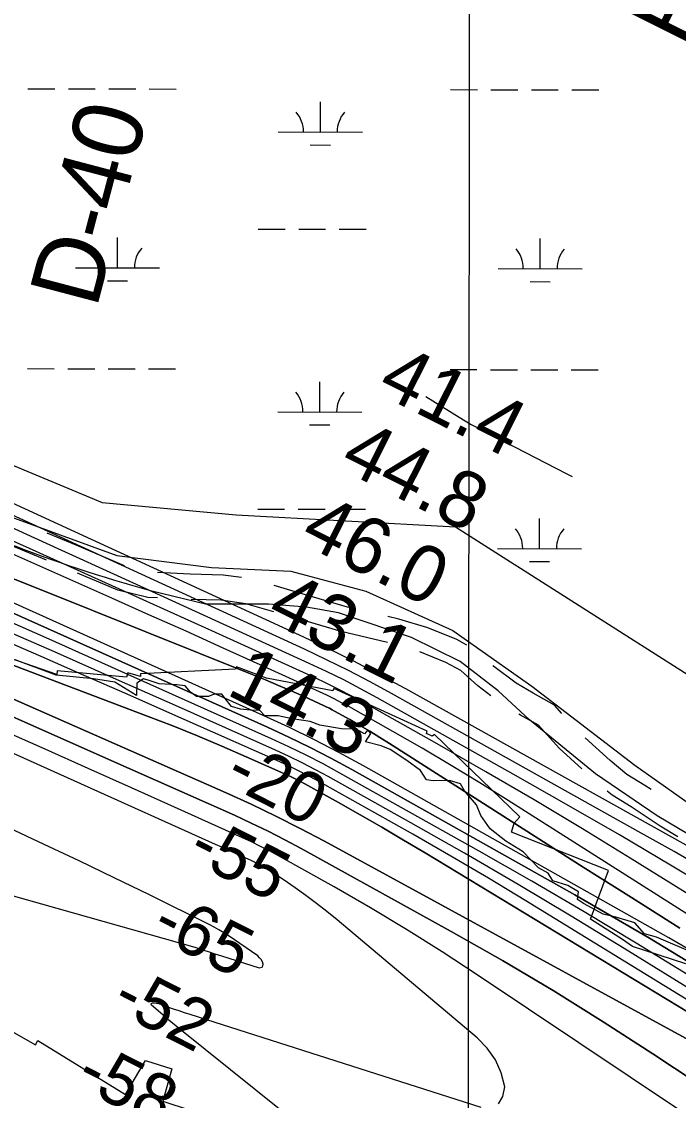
# Model space of a CAD drawing. Extents: x 3219052 to 3256913, y 800770 to 826146.
# Drawn here: x 3238412 to 3239192, y 815198 to 816480 of the extents above; entities that cross this region are included whole.
import ezdxf

# ---------------------------------------------------------------- set-up
doc = ezdxf.new("R2010")
doc.units = 0
for name, color, linetype in [('V-GRID-MAJR', 7, 'Continuous'), ('V-RIVR-EDGE', 7, 'Continuous'), ('V-RIVR-RANG', 7, 'Continuous'), ('V-RIVR-RANG-IDEN', 7, 'Continuous'), ('V-ROAD-CNTR', 7, 'Continuous'), ('V-RRAP-RVMT', 7, 'Continuous'), ('V-SITE-VEGE', 7, 'Continuous'), ('V-TOPO-DPTH', 7, 'Continuous'), ('V-TOPO-MAJR', 7, 'Continuous'), ('V-TOPO-MINR', 7, 'Continuous'), ('V-TOPO-WATR', 7, 'Continuous'), ('V-WETL-SWMP', 7, 'Continuous')]:
    doc.layers.add(name, color=color, linetype=linetype)

msp = doc.modelspace()

# ---------------------------------------------------------------- linework, layer by layer
at = {"layer": 'V-GRID-MAJR'}
msp.add_spline([(3238932.4, 806165.2), (3238939.4, 812224), (3238946.5, 818286.2), (3238953.5, 824348.4), (3238953.5, 824351.8)], degree=3, dxfattribs=at)
at = {"layer": 'V-RIVR-EDGE'}
for points in [[(3239117.7, 815415.8), (3239102.5, 815419.3), (3239079.5, 815432), (3239072.1, 815436.8), (3239073.5, 815445.9), (3239060.9, 815453.3), (3239043.1, 815459), (3239037.4, 815468.1), (3239025.7, 815474.3), (3239007.5, 815493.4), (3238987.1, 815506.1), (3238968.5, 815520.9), (3238957.2, 815536.6), (3238952.4, 815549.2), (3238938.1, 815565.8), (3238933.4, 815574), (3238920.3, 815578), (3238900.8, 815577.6), (3238893, 815578.9), (3238885.6, 815590.2), (3238869.5, 815602), (3238849.6, 815615.1), (3238839.2, 815619.5), (3238820.5, 815623.9), (3238826.6, 815633.8), (3238823.1, 815638.2), (3238819.2, 815633.4), (3238812.7, 815637.3), (3238807.9, 815639.1), (3238791.8, 815639.6), (3238766.2, 815644), (3238754.5, 815648.4), (3238733.2, 815651.5), (3238716.7, 815655), (3238701, 815655), (3238695, 815661.5), (3238683.7, 815661.6), (3238671.9, 815662.9), (3238661.1, 815666), (3238653.7, 815675.6), (3238649.8, 815680.8), (3238640.7, 815680.8), (3238634.1, 815677.8), (3238619.8, 815677.8), (3238612.4, 815683.1), (3238606.4, 815690.5), (3238596.4, 815691.8), (3238575.5, 815693.1), (3238563.3, 815697.1), (3238556.8, 815698.8), (3238549, 815693.6), (3238548.5, 815679.3), (3238522.9, 815695), (3238497.3, 815699), (3238452.9, 815703.4), (3238404.3, 815721.4)], [(3239204.1, 815375.6), (3239165.9, 815391.8), (3239151.6, 815396.1), (3239140.3, 815409.2), (3239117.7, 815415.8)]]:
    msp.add_lwpolyline(points, dxfattribs=at)
at = {"layer": 'V-ROAD-CNTR'}
for points in [[(3238441.5, 815839.9), (3238399.5, 815857.4), (3238347.3, 815872.9)], [(3238534.3, 815833.2), (3238476.8, 815857.7), (3238442.2, 815872.1)], [(3238566.7, 815803.2), (3238555.6, 815806.2), (3238544.6, 815809.4), (3238533.6, 815812.5), (3238522.7, 815815.8), (3238511.7, 815819.2), (3238500.8, 815822.6), (3238489.9, 815826.1), (3238479, 815829.6), (3238468.2, 815833.3), (3238457.4, 815837), (3238446.6, 815840.8), (3238435.8, 815844.7), (3238425.1, 815848.6), (3238414.4, 815852.7), (3238403.7, 815856.8)], [(3238573.3, 815795.2), (3238561.9, 815795.7), (3238526.1, 815804.1), (3238478.4, 815824.4)], [(3238673.1, 815819.2), (3238651.5, 815822.3), (3238612.1, 815823.4), (3238573.4, 815825.2)], [(3239794.4, 815150.8), (3239388.8, 815404.4), (3239166.9, 815536), (3239093.4, 815585.9), (3239015.1, 815650.4), (3238978, 815684.8), (3238932.9, 815719.4), (3238874.9, 815748), (3238822.4, 815765.9), (3238788.2, 815777.5), (3238750.3, 815784), (3238705.1, 815787.6), (3238630.2, 815787.6), (3238566.7, 815803.2)], [(3238808, 815782.1), (3238799.1, 815784.2), (3238731.9, 815804), (3238711.9, 815809.7)], [(3238711.6, 815778.6), (3238678.1, 815788.2), (3238649, 815792.3), (3238613.2, 815793.4)], [(3238940.6, 815739.1), (3238929, 815745.6), (3238894.3, 815759.5), (3238860, 815769.8), (3238846.9, 815772.9)], [(3238846.7, 815742.1), (3238791.4, 815755.2), (3238750, 815767.4)], [(3238969.3, 815678.9), (3238953.9, 815690.6), (3238933.7, 815708.7), (3238916, 815718.5), (3238885, 815730.9)], [(3239053.6, 815657.8), (3239044.9, 815667.5), (3239019.6, 815681.9), (3238999.4, 815693.6), (3238973, 815713.7), (3238972, 815714.6)], [(3239077.5, 815591.9), (3239050.5, 815616.6), (3239025.9, 815643.8), (3239004.7, 815655.9), (3239002.7, 815657.1)], [(3239159.6, 815567.3), (3239152.3, 815572.3), (3239130.8, 815585.2), (3239110.9, 815601.9), (3239081.3, 815629)], [(3239191.5, 815511.3), (3239170.5, 815523.7), (3239136.1, 815547), (3239113.3, 815560.7), (3239107.6, 815565.5)]]:
    msp.add_lwpolyline(points, dxfattribs=at)
at = {"layer": 'V-RRAP-RVMT'}
for points in [[(3237377.9, 815921.9), (3237418.6, 815904.3), (3237423.2, 815901.5), (3237419.2, 815888.9), (3237430.6, 815884.4), (3237430.1, 815883.5), (3237533.8, 815818), (3237531.6, 815812.2), (3237547.5, 815806.1), (3237544, 815796.2), (3237571.4, 815784.5), (3237560.1, 815763.9), (3237653, 815706.7), (3237656, 815712.1), (3237928.6, 815546.1), (3237929.8, 815548), (3237935.3, 815544.9), (3237933.7, 815539.8), (3237961.3, 815530.1), (3238428.6, 815264.2), (3238431.4, 815269.1)], [(3239087.5, 815413.2), (3239109.2, 815471.1), (3238993.9, 815516.6), (3238996.8, 815527.3), (3239003.7, 815534.8), (3238902.4, 815632.6), (3238899.4, 815630.8), (3238892.9, 815634.1), (3238893.8, 815636.6), (3238782.9, 815687.6), (3238781.5, 815684.6), (3238703, 815699.6), (3238667.1, 815713.1), (3238666, 815710.3), (3238553.2, 815704.7), (3238553.2, 815701.7), (3238538, 815706.1), (3238536.6, 815700.9), (3238454.2, 815708.5), (3238453.8, 815704.1), (3238294, 815759.4)], [(3239201, 815360.4), (3239137.5, 815380.7), (3239125.5, 815389.2), (3239087.5, 815413.2)], [(3238431.4, 815269.1), (3238535.4, 815204.9), (3238559.2, 815245.3), (3238590.6, 815235.4), (3238579.8, 815197), (3238707, 815155.3), (3238697.4, 815118.5), (3238826.8, 815078.9), (3238818.9, 815052.1), (3238942.7, 815013.5)]]:
    msp.add_lwpolyline(points, dxfattribs=at)
at = {"layer": 'V-SITE-VEGE'}
msp.add_lwpolyline([(3237307.9, 816549.6), (3237406.5, 816486.8), (3237522.9, 816415.1), (3237630.5, 816370.2), (3237738, 816343.3), (3237791.8, 816316.4), (3237827.6, 816244.7), (3237917.2, 816190.9), (3238006.8, 816119.1), (3238078.5, 816056.4), (3238114.3, 816032.5), (3238318.4, 815920.7), (3238525, 815845.5), (3238637.7, 815831.4), (3238731.6, 815826.7), (3238820.9, 815803.2), (3238924.2, 815756.2), (3239018.1, 815690.4), (3239140.2, 815596.4), (3239220, 815540)], dxfattribs=at)
at = {"layer": 'V-TOPO-DPTH'}
for points in [[(3238375.2, 815828.5), (3238433.1, 815805.3), (3238686, 815704), (3238701.5, 815697.7), (3238716.9, 815691.2), (3238732.1, 815684.6), (3238747.4, 815677.8), (3238771.5, 815666.9), (3238774.6, 815665.4), (3238777.7, 815663.9), (3238780.7, 815662.3), (3238783.7, 815660.7), (3238801.8, 815650.5), (3238813.7, 815643.6), (3238825.6, 815636.6), (3238837.4, 815629.4), (3238849, 815622), (3238964.8, 815548.2), (3239021.9, 815511.7), (3239079.1, 815475.3), (3239136.3, 815439), (3239193.6, 815402.7)], [(3238388.9, 815783.1), (3238703.9, 815641.6), (3238729.4, 815629.8), (3238754.6, 815617.5), (3238779.4, 815604.6), (3238804, 815591.2), (3239069, 815442.2), (3239113.5, 815416.7), (3239157.6, 815390.8), (3239201.4, 815364.2)], [(3239201.4, 815364.2), (3239157.6, 815390.8), (3239113.5, 815416.7), (3239069, 815442.2), (3238804, 815591.2), (3238779.4, 815604.6), (3238754.6, 815617.5), (3238729.4, 815629.8), (3238703.9, 815641.6), (3238388.9, 815783.1)], [(3239287, 815279.9), (3239127.6, 815378.7), (3239064.8, 815417), (3239001.7, 815454.7), (3238938.1, 815491.6), (3238874.1, 815528), (3238776.2, 815582.7), (3238760.9, 815591), (3238745.3, 815599), (3238729.6, 815606.7), (3238713.7, 815614), (3238598.4, 815665.5), (3238524.7, 815698.3), (3238450.9, 815730.9), (3238377.1, 815763.3)], [(3239287, 815279.9), (3239127.6, 815378.7), (3239064.8, 815417), (3239001.7, 815454.7), (3238938.1, 815491.6), (3238874.1, 815528), (3238776.2, 815582.7), (3238760.9, 815591), (3238745.3, 815599), (3238729.6, 815606.7), (3238713.7, 815614), (3238598.4, 815665.5), (3238524.7, 815698.3), (3238450.9, 815730.9), (3238377.1, 815763.3)], [(3238317, 815747.3), (3238562.3, 815654.3), (3238591.6, 815642.9), (3238620.8, 815631.2), (3238649.9, 815618.9), (3238678.7, 815606.4), (3238723.6, 815586.5), (3238729.9, 815583.6), (3238736.1, 815580.6), (3238742.3, 815577.4), (3238748.4, 815574.1), (3238788.3, 815551.9), (3238814.2, 815537.3), (3238840, 815522.5), (3238865.7, 815507.4), (3238891.2, 815492.2), (3239296.3, 815246.6)], [(3238317, 815747.3), (3238562.3, 815654.3), (3238591.6, 815642.9), (3238620.8, 815631.2), (3238649.9, 815618.9), (3238678.7, 815606.4), (3238723.6, 815586.5), (3238729.9, 815583.6), (3238736.1, 815580.6), (3238742.3, 815577.4), (3238748.4, 815574.1), (3238788.3, 815551.9), (3238814.2, 815537.3), (3238840, 815522.5), (3238865.7, 815507.4), (3238891.2, 815492.2), (3239296.3, 815246.6)], [(3239209.1, 815267.2), (3238771.6, 815506), (3238742.8, 815521.2), (3238713.9, 815535.9), (3238684.5, 815549.9), (3238655, 815563.4), (3238285.1, 815726.3)], [(3238285.1, 815726.3), (3238655, 815563.4), (3238684.5, 815549.9), (3238713.9, 815535.9), (3238742.8, 815521.2), (3238771.6, 815506), (3239209.1, 815267.2)], [(3239240.2, 815201.5), (3239161.6, 815253.5), (3239102.8, 815291.5), (3239043.4, 815328.5), (3238983.1, 815364.1), (3238922.3, 815398.7), (3238744.2, 815497.2), (3238724.6, 815507.7), (3238704.9, 815517.9), (3238684.8, 815527.5), (3238664.7, 815536.8), (3238508.4, 815606.3), (3238422.2, 815644.6), (3238336, 815682.8)], [(3238336, 815682.8), (3238422.2, 815644.6), (3238508.4, 815606.3), (3238664.7, 815536.8), (3238684.8, 815527.5), (3238704.9, 815517.9), (3238724.6, 815507.7), (3238744.2, 815497.2), (3238922.3, 815398.7), (3238983.1, 815364.1), (3239043.4, 815328.5), (3239102.8, 815291.5), (3239161.6, 815253.5), (3239240.2, 815201.5)]]:
    msp.add_lwpolyline(points, dxfattribs=at)
at = {"layer": 'V-TOPO-MAJR'}
for points in [[(3239247.2, 815438.6), (3239184.8, 815476.2), (3239122.1, 815513.4), (3239059, 815549.8), (3238995.6, 815585.8), (3238834.4, 815676.3), (3238814.5, 815687.1), (3238794.5, 815697.6), (3238774.2, 815707.6), (3238753.7, 815717.3), (3238530.3, 815819.4), (3238455.5, 815853.5), (3238380.5, 815887.5)], [(3239255.4, 815144.8), (3238953.2, 815347.2), (3238911.4, 815374.5), (3238869.2, 815401.1), (3238826.4, 815426.7), (3238783.2, 815451.6), (3238717, 815488.7), (3238706.5, 815494.4), (3238695.9, 815499.9), (3238685.1, 815505.1), (3238674.3, 815510.2), (3238593.7, 815546.3), (3238542.5, 815569.3), (3238491.2, 815592.3), (3238440, 815615.2), (3238388.7, 815638.1)]]:
    msp.add_lwpolyline(points, dxfattribs=at)
at = {"layer": 'V-TOPO-MINR'}
for points in [[(3238892, 816034.3), (3238931.8, 816009.8), (3238938.9, 816005.5), (3238946, 816001.3), (3238953.2, 815997.4), (3238960.6, 815993.5), (3239059.4, 815942.5), (3239065.9, 815939.4)], [(3239304, 815444), (3238868.3, 815686.9), (3238837.1, 815703.8), (3238805.7, 815720.2), (3238774, 815735.8), (3238741.9, 815751), (3238168.5, 816014.6)], [(3239342.9, 815330.3), (3238990, 815554.2), (3238956.1, 815575.4), (3238922, 815596.1), (3238887.6, 815616.4), (3238853, 815636.3), (3238800.6, 815665.9), (3238792, 815670.6), (3238783.3, 815675.1), (3238774.5, 815679.5), (3238765.6, 815683.6), (3238695.4, 815715.5), (3238651.4, 815735.5), (3238607.3, 815755.4), (3238563.2, 815775.1), (3238519, 815794.8), (3238126.8, 815969.2)], [(3237309.9, 815963.6), (3237398.2, 815910.1), (3237485.9, 815855.7), (3237572.6, 815799.8), (3237658.8, 815743.1), (3237881.1, 815585.8), (3237889.5, 815583.3), (3237918.4, 815577.3), (3237922.5, 815576.6), (3238617.8, 815380.1), (3238625.7, 815377.4), (3238633.5, 815374.8), (3238641.3, 815372.2), (3238649.2, 815369.7), (3238694.2, 815355.7), (3238697.8, 815356.4)], [(3239225.9, 815471.3), (3239187, 815493.6), (3239148, 815515.7), (3238851.3, 815681.6), (3238825.8, 815695.4), (3238800.1, 815708.9), (3238774.1, 815721.7), (3238747.8, 815734.1), (3238351.5, 815915.8)], [(3239291.7, 815262.9), (3239010.8, 815435), (3238966.4, 815461.9), (3238921.8, 815488.3), (3238876.8, 815514.2), (3238831.6, 815539.8), (3238762.3, 815578.4), (3238751.6, 815584.2), (3238740.7, 815589.8), (3238729.7, 815595.1), (3238718.7, 815600.2), (3238639.2, 815635.6), (3238588.2, 815658.2), (3238537.2, 815680.7), (3238486.2, 815703), (3238435.1, 815725.3), (3238084.7, 815877.4)], [(3239333.8, 815362.1), (3239134.8, 815485.8), (3239078, 815520.6), (3239020.8, 815555), (3238963.3, 815588.5), (3238905.4, 815621.6), (3238817.5, 815671.1), (3238803.2, 815678.8), (3238788.9, 815686.4), (3238774.3, 815693.5), (3238759.7, 815700.4), (3238642.2, 815754), (3238568.7, 815787.4), (3238495.1, 815820.6), (3238421.5, 815853.8), (3238347.8, 815886.7)], [(3239207.1, 815375.7), (3239180.5, 815391), (3238817.9, 815595.4), (3238788.7, 815611.3), (3238759.2, 815626.8), (3238729.2, 815641.4), (3238699, 815655.5), (3238248, 815858.7)], [(3239193.6, 815402.7), (3239136.3, 815439), (3239079.1, 815475.3), (3239021.9, 815511.7), (3238964.8, 815548.2), (3238849, 815622), (3238837.4, 815629.4), (3238825.6, 815636.6), (3238813.7, 815643.6), (3238801.8, 815650.5), (3238783.7, 815660.7), (3238780.7, 815662.3), (3238777.7, 815663.9), (3238774.6, 815665.4), (3238771.5, 815666.9), (3238747.4, 815677.8), (3238732.1, 815684.6), (3238716.9, 815691.2), (3238701.5, 815697.7), (3238686, 815704), (3238433.1, 815805.3), (3238375.2, 815828.5)], [(3239203.4, 815347.1), (3239142, 815385), (3239080.3, 815422.2), (3239018, 815458.6), (3238955.4, 815494.3), (3238790.1, 815586.9), (3238770.1, 815597.8), (3238749.9, 815608.3), (3238729.5, 815618.2), (3238708.8, 815627.8), (3238526.6, 815709.4), (3238444.7, 815745.9), (3238362.8, 815782.3)], [(3238978.5, 815194.1), (3238983.6, 815202.6), (3238986, 815214.2), (3238981.4, 815230.9), (3238974.8, 815246.3), (3238965, 815260), (3238953.1, 815272.5), (3238786.7, 815412.4), (3238774.5, 815422.3), (3238762.3, 815432), (3238749.7, 815441.3), (3238737, 815450.4), (3238722.8, 815460.3), (3238717, 815464.2), (3238711.1, 815468), (3238705.2, 815471.6), (3238699.1, 815475.1), (3238689.9, 815480.3), (3238688.4, 815481.1), (3238685.4, 815482.6), (3238683.9, 815483.4), (3238672, 815488.7), (3238664.6, 815492.1), (3238657.1, 815495.5), (3238649.6, 815498.9), (3238642.1, 815502.2), (3238046.9, 815770.4)], [(3239287, 815279.9), (3239127.6, 815378.7), (3239064.8, 815417), (3239001.7, 815454.7), (3238938.1, 815491.6), (3238874.1, 815528), (3238776.2, 815582.7), (3238760.9, 815591), (3238745.3, 815599), (3238729.6, 815606.7), (3238713.7, 815614), (3238598.4, 815665.5), (3238524.7, 815698.3), (3238450.9, 815730.9), (3238377.1, 815763.3)], [(3239296.3, 815246.6), (3238891.2, 815492.2), (3238865.7, 815507.4), (3238840, 815522.5), (3238814.2, 815537.3), (3238788.3, 815551.9), (3238748.4, 815574.1), (3238742.3, 815577.4), (3238736.1, 815580.6), (3238729.9, 815583.6), (3238723.6, 815586.5), (3238678.7, 815606.4), (3238649.9, 815618.9), (3238620.8, 815631.2), (3238591.6, 815642.9), (3238562.3, 815654.3), (3238317, 815747.3)], [(3239209.1, 815267.2), (3238771.6, 815506), (3238742.8, 815521.2), (3238713.9, 815535.9), (3238684.5, 815549.9), (3238655, 815563.4), (3238285.1, 815726.3)], [(3239240.2, 815201.5), (3239161.6, 815253.5), (3239102.8, 815291.5), (3239043.4, 815328.5), (3238983.1, 815364.1), (3238922.3, 815398.7), (3238744.2, 815497.2), (3238724.6, 815507.7), (3238704.9, 815517.9), (3238684.8, 815527.5), (3238664.7, 815536.8), (3238508.4, 815606.3), (3238422.2, 815644.6), (3238336, 815682.8)], [(3238697.8, 815356.4), (3238698.6, 815357.9), (3238698.9, 815359.9), (3238698, 815362.8), (3238696.6, 815365.4), (3238694.7, 815367.6), (3238692.5, 815369.6), (3238657.5, 815393.8), (3238652, 815397.3), (3238646.4, 815400.8), (3238640.7, 815404), (3238634.9, 815407), (3238563.7, 815442.1), (3238522.1, 815462.4), (3238480.4, 815482.5), (3238438.6, 815502.2), (3238396.7, 815521.8)], [(3238812.5, 815111.8), (3238600, 815282.5), (3238595.6, 815286.1), (3238591.1, 815289.8), (3238586.7, 815293.5), (3238582.4, 815297.2), (3238566.4, 815311), (3238566, 815312), (3238566, 815312.9), (3238566.6, 815313.5), (3238567.6, 815314), (3238569.9, 815313.8), (3238574.5, 815313), (3238576.8, 815312.3), (3238585.4, 815309.3), (3238592, 815307), (3238598.6, 815304.8), (3238605.2, 815302.6), (3238611.8, 815300.4), (3238957.4, 815189.8)]]:
    msp.add_lwpolyline(points, dxfattribs=at)
at = {"layer": 'V-TOPO-WATR'}
msp.add_lwpolyline([(3239201.4, 815364.2), (3239157.6, 815390.8), (3239113.5, 815416.7), (3239069, 815442.2), (3238804, 815591.2), (3238779.4, 815604.6), (3238754.6, 815617.5), (3238729.4, 815629.8), (3238703.9, 815641.6), (3238388.9, 815783.1)], dxfattribs=at)
at = {"layer": 'V-WETL-SWMP'}
for p, q in [((3238419.5, 816400.2), (3238451.5, 816400.1)), ((3238467.5, 816400.1), (3238499.5, 816400)), ((3238515.5, 816400), (3238547.5, 816399.9)), ((3238563.5, 816399.9), (3238595.5, 816399.8)), ((3238921.4, 816399.1), (3238953.4, 816399)), ((3238969.4, 816399), (3239001.4, 816398.9)), ((3239017.4, 816398.9), (3239049.4, 816398.8)), ((3239065.4, 816398.8), (3239097.4, 816398.7)), ((3238766.8, 816348.7), (3238766.8, 816384.7)), ((3238716.8, 816348.8), (3238816.8, 816348.6)), ((3238754.7, 816333.3), (3238778.7, 816333.2)), ((3238693.1, 816233.4), (3238725.1, 816233.4)), ((3238525.9, 816187.3), (3238526, 816223.3)), ((3238741.1, 816233.3), (3238773.1, 816233.3)), ((3238789.1, 816233.2), (3238821.1, 816233.2)), ((3239027.8, 816186.3), (3239027.9, 816222.3)), ((3238475.9, 816187.4), (3238575.9, 816187.2)), ((3238977.8, 816186.4), (3239077.8, 816186.2)), ((3238513.9, 816171.9), (3238537.9, 816171.9)), ((3239015.8, 816170.9), (3239039.8, 816170.8)), ((3238418.8, 816067.5), (3238450.8, 816067.4)), ((3238466.8, 816067.4), (3238498.8, 816067.3)), ((3238514.8, 816067.3), (3238546.8, 816067.2)), ((3238562.8, 816067.2), (3238594.8, 816067.1)), ((3238920.8, 816066.4), (3238952.8, 816066.4)), ((3238968.8, 816066.3), (3239000.8, 816066.3)), ((3239016.8, 816066.2), (3239048.8, 816066.2)), ((3239064.8, 816066.1), (3239096.8, 816066.1)), ((3238766.1, 816016), (3238766.1, 816052)), ((3238716.1, 816016.1), (3238816.1, 816015.9)), ((3238754, 816000.6), (3238778, 816000.6)), ((3238334, 815980.9), (3238507.6, 815908.5)), ((3238507.6, 815908.5), (3238666.8, 815894)), ((3238692.4, 815900.7), (3238724.4, 815900.7)), ((3238740.4, 815900.6), (3238772.4, 815900.6)), ((3238788.4, 815900.5), (3238820.4, 815900.5)), ((3238666.8, 815894), (3238927.3, 815879.5)), ((3239027.1, 815853.6), (3239027.2, 815889.6)), ((3238927.3, 815879.5), (3239245.6, 815676.8)), ((3238977.1, 815853.7), (3239077.1, 815853.5)), ((3239015.1, 815838.2), (3239039.1, 815838.2))]:
    msp.add_line(p, q, dxfattribs=at)
for centre, start, end in [((3238711.5, 816349.3), 359.1081, 40.6518), ((3238822, 816349.1), 139.1081, 180.6517), ((3238470.7, 816187.9), 359.1081, 40.6518), ((3238581.2, 816187.7), 139.1081, 180.6517), ((3238972.6, 816186.9), 359.1081, 40.6518), ((3239083.1, 816186.6), 139.1081, 180.6517), ((3238710.8, 816016.6), 359.1081, 40.6518), ((3238821.3, 816016.4), 139.1081, 180.6517), ((3238971.9, 815854.2), 359.1081, 40.6518), ((3239082.4, 815854), 139.1081, 180.6517)]:
    msp.add_arc(centre, 35.2, start, end, dxfattribs=at)

# ---------------------------------------------------------------- texts
at = {"layer": 'V-RIVR-RANG'}
for s, height, rotation, p in [('41.4', 67, 333.3483, (3238832.1, 816039.2)), ('44.8', 67, 333.3483, (3238787.5, 815949.7)), ('46.0', 67, 333.3483, (3238740.3, 815861.5)), ('43.1', 67, 333.3483, (3238700.3, 815769.7)), ('14.3', 67, 333.3483, (3238653.6, 815681.2)), ('-20', 60, 333.0512, (3238650.8, 815575.1)), ('-55', 60, 333.0512, (3238606.4, 815485.5)), ('-65', 60, 333.0512, (3238563.4, 815395.2)), ('-52', 60, 333.0512, (3238516.3, 815307)), ('-58', 60, 333.0512, (3238473.3, 815216.6))]:
    msp.add_text(s, height=height, rotation=rotation, dxfattribs=at).set_placement(p)
at = {"layer": 'V-RIVR-RANG-IDEN'}
for s, rotation, p in [('R-269.3', 63.4937, (3239202.4, 816445.8)), ('D-40', 75.23, (3238500.8, 816137.6))]:
    msp.add_text(s, height=83, rotation=rotation, dxfattribs=at).set_placement(p)

doc.saveas('drawing.dxf')
